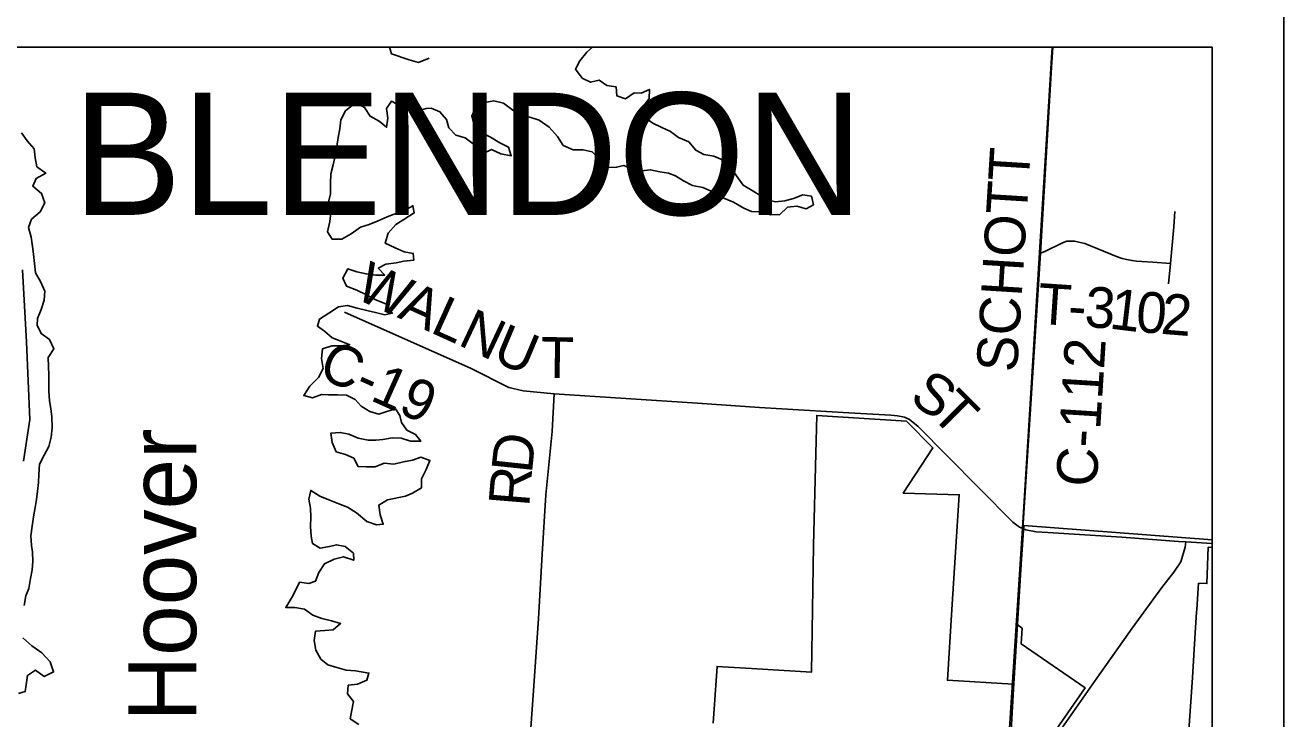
# Model space of a CAD drawing. Extents: x 0 to 34, y 0 to 22.
# Drawn here: x 7.246 to 9, y 19.964 to 20.931 of the extents above; entities that cross this region are included whole.
import ezdxf

# ---------------------------------------------------------------- set-up
doc = ezdxf.new("R2010")
doc.units = 0
for name, color, linetype in [('Default', 7, 'Continuous'), ('GM_X_Corporation', 7, 'Continuous'), ('GM_X_County_Road', 7, 'Continuous'), ('GM_X_County_Road_Text', 7, 'Continuous'), ('GM_X_Major_Lake', 7, 'Continuous'), ('GM_X_Major_Lake_Text', 7, 'Continuous'), ('GM_X_Township_Road', 7, 'Continuous'), ('GM_X_Township_Road_Text', 7, 'Continuous'), ('GM_X_Township_Text', 7, 'Continuous'), ('SH_Data', 7, 'Continuous')]:
    doc.layers.add(name, color=color, linetype=linetype)

msp = doc.modelspace()

# ---------------------------------------------------------------- linework, layer by layer
at = {"layer": 'Default'}
msp.add_lwpolyline([(8.9, 19.1966), (8.9, 20.2132), (8.6374, 20.2329), (8.6338, 20.179), (8.6233, 20.0051), (8.6057, 19.6933), (8.5782, 19.2201)], close=True, dxfattribs=at)
at = {"layer": 'GM_X_Corporation'}
for points in [[(7.2433, 20.323), (7.2522, 20.381), (7.2478, 20.4887), (7.2421, 20.5896)], [(8.683, 19.9494), (8.7229, 20.0068), (8.6339, 20.068), (8.6354, 20.0899), (8.6282, 20.0949), (8.6229, 20.0118), (8.5311, 20.0173), (8.5374, 20.1161), (8.5477, 20.276), (8.4696, 20.2784), (8.5109, 20.3414), (8.474, 20.3785), (8.3491, 20.3865), (8.3478, 20.3334), (8.3447, 20.2053), (8.3431, 20.1161), (8.3417, 20.0287), (8.2581, 20.0337), (8.2101, 20.0366), (8.2048, 19.9577)], [(8.9, 16.0691), (8.9, 20.2026), (8.8946, 20.2029), (8.8929, 20.1522), (8.8811, 20.1527), (8.8787, 20.1161), (8.8785, 20.1123), (8.8766, 20.0835), (8.8726, 20.0212), (8.8678, 19.9474)]]:
    msp.add_lwpolyline(points, dxfattribs=at)
at = {"layer": 'GM_X_County_Road'}
for points in [[(8.4511, 17.1951), (8.4574, 17.2984), (8.4834, 17.726), (8.4924, 17.8634), (8.4933, 17.8764), (8.5463, 18.6832), (8.5517, 18.8459), (8.5602, 18.986), (8.5739, 19.2101), (8.5742, 19.2159), (8.5745, 19.2215), (8.6104, 19.8358), (8.636, 20.2294), (8.6772, 20.9), (3.9336, 20.9)], [(8.6362, 20.2289), (8.6608, 20.6129), (8.6764, 20.8723), (8.6781, 20.9)], [(7.6906, 20.5304), (7.8673, 20.4521), (7.9199, 20.4253), (7.94, 20.4208), (7.9832, 20.4168)], [(7.9453, 19.445), (7.9609, 19.6428), (7.9617, 19.6607), (7.9601, 19.6645), (7.9516, 19.7386), (7.9426, 19.8187), (7.9422, 19.8278), (7.9426, 19.8396), (7.9547, 20.0094), (7.9614, 20.1033), (7.9665, 20.1933), (7.9716, 20.2761), (7.9801, 20.3643), (7.9832, 20.4168)], [(7.9832, 20.4168), (8.1827, 20.4037), (8.2693, 20.3978), (8.3938, 20.3902), (8.4524, 20.3868), (8.4615, 20.386), (8.4711, 20.384), (8.4782, 20.3809), (8.4902, 20.3711), (8.5301, 20.3306), (8.6225, 20.2378), (8.6316, 20.231), (8.6362, 20.2289)], [(8.6362, 20.2289), (8.6405, 20.227), (8.6549, 20.2243), (8.6711, 20.2232), (8.7741, 20.2168), (8.8534, 20.2109)], [(8.6874, 19.9459), (8.7068, 19.9738), (8.7395, 20.0202), (8.7885, 20.0901), (8.8301, 20.1469), (8.8468, 20.1682), (8.8566, 20.1827), (8.8626, 20.203), (8.8633, 20.2102)], [(8.8534, 20.2109), (8.8633, 20.2102), (8.9, 20.2081)]]:
    msp.add_lwpolyline(points, dxfattribs=at)
msp.add_lwpolyline([(8.9, 16.069), (8.9, 20.9), (8.6772, 20.9), (8.636, 20.2294), (8.6104, 19.8358), (8.5745, 19.2215), (8.5742, 19.2159), (8.5739, 19.2101), (8.5602, 18.986), (8.5517, 18.8459), (8.5463, 18.6832), (8.4933, 17.8764), (8.4924, 17.8634), (8.4834, 17.726), (8.4574, 17.2984), (8.4511, 17.1951), (8.4246, 16.7343), (8.4151, 16.5575), (8.4046, 16.4383), (8.3992, 16.2979), (8.3884, 16.1033), (8.4715, 16.0965), (8.5217, 16.0919)], close=True, dxfattribs=at)
at = {"layer": 'GM_X_Major_Lake'}
for points in [[(7.809, 20.8844), (7.794, 20.8786), (7.7807, 20.8821), (7.7565, 20.8905), (7.7536, 20.9)], [(8.2972, 20.6662), (8.3083, 20.6767), (8.3212, 20.6785), (8.3341, 20.6746), (8.3444, 20.6802), (8.3415, 20.6923), (8.3294, 20.694), (8.3168, 20.6892), (8.3046, 20.6859), (8.2917, 20.6845), (8.2822, 20.6865), (8.2724, 20.6919), (8.2592, 20.7), (8.2464, 20.7077), (8.237, 20.7207), (8.2292, 20.7322), (8.2186, 20.7425), (8.2054, 20.748), (8.1918, 20.7504), (8.1804, 20.7562), (8.1707, 20.7681), (8.1563, 20.7739), (8.145, 20.7824), (8.1329, 20.7878), (8.1205, 20.794), (8.1077, 20.8032), (8.1055, 20.8154), (8.1155, 20.8282), (8.1157, 20.8411), (8.1042, 20.8359), (8.0944, 20.8364), (8.0825, 20.8278), (8.0704, 20.8321), (8.0694, 20.8446), (8.0565, 20.8463), (8.0456, 20.854), (8.0338, 20.851), (8.0221, 20.8569), (8.0127, 20.8695), (8.0189, 20.8808), (8.0285, 20.8928), (8.0366, 20.9)], [(7.7698, 20.3548), (7.783, 20.3505), (7.7971, 20.3505), (7.7899, 20.36), (7.7778, 20.3658), (7.7703, 20.3768), (7.768, 20.3863), (7.762, 20.3958), (7.7499, 20.3921), (7.7385, 20.3883), (7.7263, 20.3922), (7.7139, 20.3995), (7.7056, 20.409), (7.6934, 20.4147), (7.6813, 20.4152), (7.6684, 20.4152), (7.6589, 20.4157), (7.6464, 20.4112), (7.6339, 20.4143), (7.6423, 20.4275), (7.6545, 20.4396), (7.661, 20.4521), (7.6588, 20.4658), (7.66, 20.4794), (7.6733, 20.4835), (7.6851, 20.4835), (7.698, 20.485), (7.6855, 20.4899), (7.6734, 20.4949), (7.6628, 20.5041), (7.653, 20.511), (7.656, 20.5208), (7.669, 20.5291), (7.6823, 20.5378), (7.6952, 20.5396), (7.7085, 20.5362), (7.7221, 20.5327), (7.7342, 20.53), (7.7471, 20.5269), (7.7574, 20.5291), (7.7483, 20.542), (7.7354, 20.5474), (7.7214, 20.5547), (7.7078, 20.5612), (7.6938, 20.5666), (7.6886, 20.578), (7.6954, 20.5909), (7.7079, 20.5867), (7.7208, 20.5839), (7.7345, 20.582), (7.747, 20.5823), (7.7379, 20.5918), (7.7482, 20.5975), (7.7626, 20.5993), (7.7736, 20.6015), (7.7873, 20.603), (7.7866, 20.6125), (7.7741, 20.6148), (7.7612, 20.6202), (7.7476, 20.6267), (7.7518, 20.6407), (7.7625, 20.6528), (7.7735, 20.6596), (7.788, 20.669), (7.7862, 20.6789), (7.7725, 20.6714), (7.7599, 20.6673), (7.7504, 20.6635), (7.7379, 20.6579), (7.725, 20.6526), (7.7132, 20.6489), (7.7002, 20.6395), (7.6869, 20.6323), (7.6736, 20.6324), (7.6673, 20.6426), (7.6704, 20.6567), (7.6716, 20.6692), (7.6678, 20.6821), (7.6713, 20.6954), (7.6714, 20.7098), (7.6718, 20.7235), (7.6749, 20.736), (7.6776, 20.7485), (7.6803, 20.7614), (7.6819, 20.7739), (7.6843, 20.7861), (7.6855, 20.7986), (7.6923, 20.8111), (7.7064, 20.8228), (7.7189, 20.8159), (7.7265, 20.8037), (7.7393, 20.7968), (7.7495, 20.7884), (7.7511, 20.801), (7.7493, 20.8143), (7.7561, 20.8245), (7.7682, 20.818), (7.7815, 20.813), (7.7917, 20.8106), (7.8046, 20.8144), (7.8116, 20.8149)], [(7.8116, 20.8149), (7.8237, 20.8099), (7.8331, 20.7992), (7.8364, 20.7874), (7.8458, 20.7774), (7.859, 20.7735), (7.8718, 20.7639), (7.8831, 20.7512), (7.8957, 20.7575), (7.9089, 20.7513), (7.9233, 20.7485), (7.9196, 20.7607), (7.9072, 20.7665), (7.8943, 20.7743), (7.8819, 20.7808), (7.8717, 20.7908), (7.8681, 20.8037), (7.8739, 20.8166), (7.8865, 20.8229), (7.8991, 20.8251), (7.9123, 20.8219), (7.9255, 20.8119), (7.9376, 20.8042), (7.9493, 20.8022), (7.9622, 20.7982), (7.9761, 20.7882), (7.9877, 20.7752), (7.9956, 20.763), (8.0096, 20.7568), (8.0236, 20.7566), (8.0361, 20.7539), (8.0478, 20.742), (8.0594, 20.732), (8.0701, 20.7326), (8.08, 20.7348), (8.0921, 20.7301), (8.1046, 20.7274), (8.1175, 20.7291), (8.1304, 20.7263), (8.1425, 20.7243), (8.1523, 20.7204), (8.1633, 20.7135), (8.1757, 20.7069), (8.1901, 20.7045), (8.2049, 20.6979), (8.2173, 20.6906), (8.2328, 20.6839), (8.2472, 20.6755), (8.2581, 20.6708), (8.271, 20.6703), (8.2846, 20.6663), (8.2945, 20.6666), (8.2972, 20.6662)], [(7.2404, 20.7805), (7.2483, 20.7695), (7.2582, 20.758), (7.2596, 20.7455), (7.2618, 20.7333), (7.2743, 20.7242), (7.261, 20.717), (7.2564, 20.706), (7.2685, 20.6961), (7.2733, 20.6828), (7.2668, 20.6703), (7.2546, 20.6601), (7.2504, 20.6487), (7.2541, 20.635), (7.256, 20.6221), (7.2574, 20.6115), (7.2589, 20.5982), (7.26, 20.5853), (7.2671, 20.5731), (7.2731, 20.5598), (7.2723, 20.5473), (7.2681, 20.5344), (7.2631, 20.5219), (7.2623, 20.5124), (7.2679, 20.5006), (7.2796, 20.4926), (7.2856, 20.4796), (7.2776, 20.4675), (7.2783, 20.4546), (7.2786, 20.4428), (7.2786, 20.4333), (7.2789, 20.4204), (7.2796, 20.4071), (7.2814, 20.3961), (7.2829, 20.3844), (7.2832, 20.3692), (7.282, 20.3563), (7.2785, 20.3434), (7.2724, 20.3312), (7.2659, 20.3187), (7.265, 20.3043), (7.2642, 20.2933), (7.2627, 20.2812), (7.2615, 20.2694), (7.2595, 20.2584), (7.2575, 20.2451), (7.2556, 20.2322), (7.2536, 20.2186), (7.2547, 20.2053), (7.2558, 20.1958), (7.2565, 20.1833), (7.2553, 20.1715), (7.2533, 20.1594), (7.251, 20.1453), (7.2468, 20.1351), (7.2441, 20.1218)], [(7.7109, 19.9557), (7.6985, 19.9637), (7.7004, 19.9736), (7.7035, 19.9876), (7.6948, 19.9986), (7.696, 20.0104), (7.7089, 20.0119), (7.7219, 20.0175), (7.7249, 20.0274), (7.706, 20.0305), (7.6931, 20.0313), (7.6802, 20.0352), (7.6677, 20.039), (7.6579, 20.047), (7.6507, 20.0592), (7.6485, 20.0729), (7.6505, 20.0858), (7.6634, 20.0869), (7.6752, 20.0879), (7.6854, 20.0963), (7.6726, 20.1001), (7.6593, 20.1036), (7.6468, 20.1082), (7.6351, 20.1166), (7.6214, 20.1186), (7.6089, 20.119), (7.6173, 20.1326), (7.6227, 20.1425), (7.6281, 20.1542), (7.641, 20.1523), (7.6505, 20.1553), (7.6551, 20.1674), (7.6627, 20.1799), (7.6764, 20.1863), (7.6893, 20.1896), (7.7037, 20.1846), (7.7034, 20.1945), (7.6917, 20.204), (7.6795, 20.2064), (7.6697, 20.2038), (7.6568, 20.2015), (7.6462, 20.208), (7.6443, 20.2183), (7.6436, 20.2316), (7.6437, 20.2449), (7.6434, 20.2574), (7.6412, 20.27), (7.6439, 20.2821), (7.6563, 20.2741), (7.6688, 20.2691), (7.6828, 20.2633), (7.695, 20.2587), (7.7074, 20.251), (7.7218, 20.2388), (7.7354, 20.2342), (7.7449, 20.2349), (7.7404, 20.2482), (7.7386, 20.2615), (7.7508, 20.2687), (7.7758, 20.2739), (7.7857, 20.278), (7.7979, 20.2856), (7.7979, 20.2981), (7.8045, 20.3113), (7.8098, 20.3238), (7.7973, 20.3285), (7.7856, 20.3243), (7.773, 20.3217), (7.7594, 20.3188), (7.7461, 20.32), (7.7335, 20.3151), (7.7214, 20.3151), (7.7097, 20.3156), (7.7036, 20.327), (7.6923, 20.332), (7.679, 20.3358), (7.6734, 20.3488), (7.6716, 20.3617), (7.6848, 20.3628), (7.697, 20.3604), (7.7098, 20.3551), (7.7239, 20.352), (7.7345, 20.3519), (7.744, 20.353), (7.7573, 20.3552), (7.7698, 20.3548)], [(7.2427, 20.0766), (7.2552, 20.0652), (7.2688, 20.0556), (7.2805, 20.0431), (7.2853, 20.029), (7.2724, 20.0226), (7.2603, 20.0314), (7.2489, 20.0242), (7.2469, 20.0109), (7.2457, 20.0015), (7.2362, 19.9988)]]:
    msp.add_lwpolyline(points, dxfattribs=at)
at = {"layer": 'GM_X_Township_Road'}
msp.add_line((8.8392, 20.57), (8.8421, 20.5982), dxfattribs=at)
for points in [[(8.8421, 20.5982), (8.8465, 20.6493), (8.8482, 20.671)], [(8.6608, 20.6129), (8.6671, 20.6153), (8.6915, 20.6274), (8.6977, 20.6293), (8.7024, 20.6297), (8.7087, 20.6294), (8.7142, 20.6283), (8.7225, 20.6261), (8.7668, 20.608), (8.7746, 20.6054), (8.7811, 20.6038), (8.7885, 20.6025), (8.7947, 20.6018), (8.8021, 20.6013), (8.8172, 20.6002), (8.8421, 20.5982)]]:
    msp.add_lwpolyline(points, dxfattribs=at)
at = {"layer": 'SH_Data'}
for p, q in [((9, 21), (9, 14)), ((2.1, 20.9), (8.9, 20.9)), ((8.9, 20.9), (8.9, 14.1))]:
    msp.add_line(p, q, dxfattribs=at)

# ---------------------------------------------------------------- texts
at = {"layer": 'GM_X_County_Road_Text'}
for s, height, rotation, p in [('SCHOTT', 0.05682, 86.4676, (8.6281, 20.446)), ('W', 0.0568, 335.6824, (7.703, 20.5508)), ('A', 0.0568, 335.6804, (7.763, 20.5237)), ('L', 0.0568, 335.6415, (7.8086, 20.5031)), ('N', 0.0568, 334.8002, (7.8471, 20.4857)), ('U', 0.0568, 337.2483, (7.8947, 20.4633)), ('T', 0.0568, 359.1681, (7.9639, 20.4392)), ('C-112', 0.05682, 86.4063, (8.739, 20.2859)), ('C-19', 0.05682, 335.8976, (7.6518, 20.4412)), ('S', 0.0568, 326.6921, (8.4762, 20.4062)), ('T', 0.0568, 314.803, (8.5058, 20.3872)), ('D', 0.0568, 83.9784, (7.9519, 20.3046)), ('R', 0.0568, 85.319, (7.9481, 20.2584))]:
    msp.add_text(s, height=height, rotation=rotation, dxfattribs=at).set_placement(p)
at = {"layer": 'GM_X_Major_Lake_Text'}
msp.add_text('Hoover', height=0.09469, rotation=90.0027, dxfattribs=at).set_placement((7.4841, 19.96))
at = {"layer": 'GM_X_Township_Road_Text'}
for s, rotation, p in [('T', 356.1831, (8.6556, 20.5145)), ('3', 355.9896, (8.7212, 20.5101)), ('1', 353.219, (8.7554, 20.5078)), ('0', 355.2767, (8.7924, 20.5034)), ('2', 355.3872, (8.8274, 20.5005)), ('-', 356.1569, (8.698, 20.5117))]:
    msp.add_text(s, height=0.0568, rotation=rotation, dxfattribs=at).set_placement(p)
at = {"layer": 'GM_X_Township_Text'}
msp.add_text('BLENDON', height=0.17045, rotation=0, dxfattribs=at).set_placement((7.3119, 20.6661))

doc.saveas('drawing.dxf')
